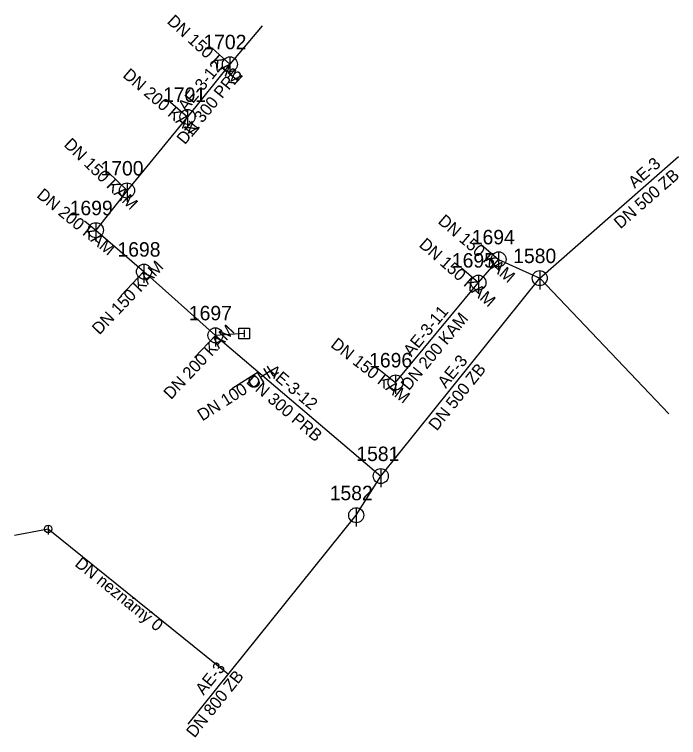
# Model space of a CAD drawing. Extents: x -494296.5 to -494208.1, y -1126934.1 to -1126837.8.
import ezdxf

# ---------------------------------------------------------------- set-up
doc = ezdxf.new("R2010")
doc.units = 0
for name, color, linetype in [('_pripojka_kanal_destova_priblizne_', 7, 'Continuous'), ('_pripojka_kanal_jednotna_priblizne_', 7, 'Continuous'), ('_pripojka_kanal_splaskova_priblizne_', 7, 'Continuous'), ('_stoka_jednotna_smvak_prevzato_z_dokumentace_', 7, 'Continuous'), ('Default', 7, 'Continuous'), ('MoLevel 119', 7, 'Continuous'), ('MoLevel 120', 7, 'Continuous'), ('MoLevel 124', 7, 'Continuous'), ('MoLevel 57', 7, 'Continuous'), ('MoLevel 63', 7, 'Continuous'), ('MoLevel 68', 7, 'Continuous'), ('MoLevel 69', 7, 'Continuous')]:
    doc.layers.add(name, color=color, linetype=linetype)

# ---------------------------------------------------------------- blocks, each defined once
blk = doc.blocks.new('_vpust_')
at = {"layer": 'Default'}
blk.add_line((0, 0.000025), (0, -0.000025), dxfattribs=at)
blk.add_lwpolyline([(-0.000035, 0.000035), (0.000035, 0.000035), (0.000035, -0.000035), (-0.000035, -0.000035), (-0.000035, 0.000035)], dxfattribs=at)
blk = doc.blocks.new('_sachta_kanal_prip_')
at = {"layer": 'Default'}
blk.add_line((0, 0.00005), (0, -0.000075), dxfattribs=at)
blk.add_circle((0, 0), 0.00005, dxfattribs=at)
blk = doc.blocks.new('_sachta_kanal_prevzato_z_dokumentace_')
at = {"layer": 'Default'}
blk.add_line((0, 0.00005), (0, -0.000075), dxfattribs=at)
blk.add_circle((0, 0), 0.00005, dxfattribs=at)

msp = doc.modelspace()

# ---------------------------------------------------------------- linework, layer by layer
at = {"layer": '_pripojka_kanal_destova_priblizne_'}
msp.add_line((-494265.946, -1126880.26), (-494269.78, -1126880.499), dxfattribs=at)
at = {"layer": '_pripojka_kanal_jednotna_priblizne_'}
for p, q in [((-494270.205, -1126842.245), (-494267.85, -1126844.4)), ((-494276.065, -1126849.2), (-494273.498, -1126851.412)), ((-494284.104, -1126858.738), (-494281.55, -1126861.21)), ((-494287.212, -1126865.256), (-494285.699, -1126866.5)), ((-494234.4, -1126868.383), (-494232.071, -1126870.38)), ((-494237.021, -1126871.501), (-494234.761, -1126873.48)), ((-494282.362, -1126875.217), (-494279.29, -1126872.02)), ((-494272.55, -1126883.448), (-494269.78, -1126880.5)), ((-494248.233, -1126884.849), (-494245.78, -1126886.77)), ((-494267.61, -1126887.599), (-494264.069, -1126885.36)), ((-494296.534, -1126907.112), (-494292.05, -1126906.284)), ((-494292.05, -1126906.284), (-494268.051, -1126925.628))]:
    msp.add_line(p, q, dxfattribs=at)
at = {"layer": '_pripojka_kanal_splaskova_priblizne_'}
msp.add_line((-494209.388, -1126890.945), (-494226.599, -1126872.879), dxfattribs=at)
at = {"layer": '_stoka_jednotna_smvak_prevzato_z_dokumentace_'}
for p, q in [((-494263.532, -1126839.291), (-494267.85, -1126844.4)), ((-494267.85, -1126844.4), (-494273.498, -1126851.412)), ((-494273.498, -1126851.412), (-494281.55, -1126861.21)), ((-494226.6, -1126872.88), (-494208.137, -1126856.703)), ((-494281.55, -1126861.21), (-494285.7, -1126866.5)), ((-494285.699, -1126866.5), (-494279.29, -1126872.02)), ((-494234.76, -1126873.48), (-494232.07, -1126870.38)), ((-494232.07, -1126870.38), (-494226.6, -1126872.88)), ((-494279.29, -1126872.02), (-494269.78, -1126880.5)), ((-494247.76, -1126899.24), (-494226.6, -1126872.88)), ((-494245.78, -1126886.77), (-494234.76, -1126873.48)), ((-494269.78, -1126880.5), (-494247.76, -1126899.24)), ((-494251.028, -1126904.46), (-494247.76, -1126899.24)), ((-494273.388, -1126932.265), (-494251.028, -1126904.46))]:
    msp.add_line(p, q, dxfattribs=at)

# ---------------------------------------------------------------- block references
at = {"layer": 'MoLevel 119', "xscale": 20000, "yscale": 20000}
for p in [(-494267.85, -1126844.4), (-494273.498, -1126851.412), (-494281.55, -1126861.21), (-494285.699, -1126866.5), (-494232.07, -1126870.38), (-494279.29, -1126872.02), (-494234.76, -1126873.48), (-494226.6, -1126872.88), (-494269.78, -1126880.5), (-494245.78, -1126886.77), (-494247.76, -1126899.24), (-494251.028, -1126904.459)]:
    msp.add_blockref('_sachta_kanal_prevzato_z_dokumentace_', p, dxfattribs=at)
at = {"layer": 'MoLevel 57', "xscale": 10000, "yscale": 10000}
msp.add_blockref('_sachta_kanal_prip_', (-494292.05, -1126906.284), dxfattribs=at)
at = {"layer": 'MoLevel 63', "xscale": 20000, "yscale": 20000}
msp.add_blockref('_vpust_', (-494265.946, -1126880.26), dxfattribs=at)

# ---------------------------------------------------------------- texts
at = {"layer": 'MoLevel 120'}
for s, p in [('1702', (-494271.381, -1126842.4)), ('1701', (-494276.754, -1126849.412)), ('1700', (-494285.081, -1126859.21)), ('1699', (-494289.184, -1126864.5)), ('1694', (-494235.647, -1126868.38)), ('1698', (-494282.821, -1126870.02)), ('1695', (-494238.291, -1126871.48)), ('1580', (-494230.131, -1126870.88)), ('1697', (-494273.311, -1126878.5)), ('1696', (-494249.311, -1126884.77)), ('1581', (-494251.016, -1126897.24)), ('1582', (-494254.559, -1126902.459))]:
    msp.add_text(s, height=1.9259, dxfattribs=at).set_placement(p)
at = {"layer": 'MoLevel 124'}
for s, height, rotation, p in [('DN 150 KAM', 1.6049, 317.54523, (-494276.314, -1126838.832)), ('DN 200 KAM', 1.6049, 319.25881, (-494282.223, -1126846.014)), ('DN 150 KAM', 1.6049, 315.94454, (-494290.059, -1126855.21)), ('DN 200 KAM', 1.6049, 320.59371, (-494293.681, -1126862.018)), ('DN 150 KAM', 1.6049, 319.38908, (-494240.26, -1126865.472)), ('DN 150 KAM', 1.6049, 318.79738, (-494242.78, -1126868.593)), ('DN 150 KAM', 1.6049, 46.14395, (-494285.233, -1126880.521)), ('DN 200 KAM', 1.6049, 46.79399, (-494275.691, -1126889.138)), ('DN 150 KAM', 1.6049, 321.93523, (-494254.543, -1126881.946)), ('DN 100 CHL', 1.6049, 32.31605, (-494271.529, -1126891.978)), ('DN neznámý 0', 1.60494, 321.12868, (-494288.609, -1126911.119))]:
    msp.add_text(s, height=height, rotation=rotation, dxfattribs=at).set_placement(p)
at = {"layer": 'MoLevel 68'}
for s, rotation, p in [('DN 300 PRB', 51.14938, (-494273.836, -1126855.19)), ('DN 500 ZB', 41.22526, (-494215.857, -1126866.401)), ('DN 200 KAM', 50.33465, (-494244.01, -1126887.95)), ('DN 500 ZB', 51.24489, (-494240.306, -1126893.318)), ('DN 300 PRB', 319.60074, (-494265.776, -1126886.815)), ('DN 800 ZB', 51.19467, (-494272.562, -1126934.2))]:
    msp.add_text(s, height=1.6049, rotation=rotation, dxfattribs=at).set_placement(p)
at = {"layer": 'MoLevel 69'}
for s, rotation, p in [('AE-3-12', 51.14938, (-494273.671, -1126850.827)), ('AE-3', 41.22526, (-494213.954, -1126861)), ('AE-3-11', 50.33465, (-494243.685, -1126883.443)), ('AE-3', 51.24489, (-494239.094, -1126887.644)), ('AE-3-12', 319.60074, (-494263.019, -1126885.454)), ('AE-3', 51.19467, (-494271.346, -1126928.527))]:
    msp.add_text(s, height=1.6049, rotation=rotation, dxfattribs=at).set_placement(p)

doc.saveas('drawing.dxf')
